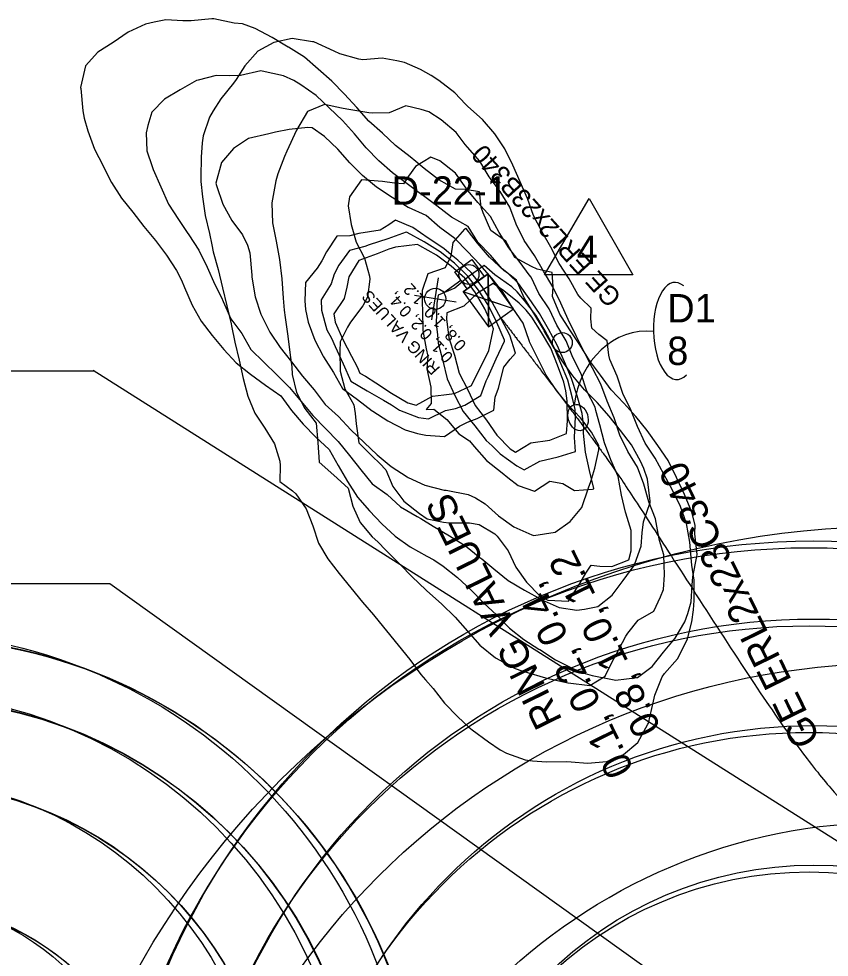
# Model space of a CAD drawing. Extents: x 1638506 to 1658005, y 834807 to 846788.
# Drawn here: x 1640682.9 to 1641025.5, y 842698.3 to 843094.9 of the extents above; entities that cross this region are included whole.
import ezdxf

# ---------------------------------------------------------------- set-up
doc = ezdxf.new("R2010")
doc.units = 0
for name, color, linetype in [('Default', 7, 'Continuous'), ('Old_Level_1', 7, 'Continuous'), ('Old_Level_2', 7, 'Continuous'), ('Old_Level_4', 7, 'Continuous'), ('Scratch_Level_0', 7, 'Continuous')]:
    doc.layers.add(name, color=color, linetype=linetype)

msp = doc.modelspace()

# ---------------------------------------------------------------- linework, layer by layer
at = {"layer": 'Default'}
for p, q in [((1640881.43, 842964.72), (1640881.28, 842987.13)), ((1640857.47, 842967.73), (1640860.34, 842985.39)), ((1640869.79, 842984.38), (1640862.53, 842979.16)), ((1640891.96, 842972.29), (1640870.76, 842979.57)), ((1640867.71, 842975.13), (1640850.08, 842978.02)), ((1640858.89, 842976.55), (1640858.89, 842976.55)), ((1640863.36, 842975.84), (1640863.36, 842975.84)), ((1640507.38, 842946.07), (1640714.43, 842946.07)), ((1640714.3, 842946.43), (1641119.83, 842689.85)), ((1640511.86, 842856.33), (1640721.43, 842856.33)), ((1640721.43, 842856.33), (1641083.08, 842597.13))]:
    msp.add_line(p, q, dxfattribs=at)
for points in [[(1640942.48, 842986.7), (1640905.09, 842986.7), (1640923.92, 843018.97)], [(1640879.64, 842985.95), (1640872.4, 842980.75), (1640867.18, 842988.02), (1640874.42, 842993.22)], [(1640891.96, 842972.29), (1640881.28, 842987.13), (1640870.76, 842979.57), (1640881.43, 842964.72)], [(1640881.36, 842975.93), (1640870.76, 842979.57), (1640881.28, 842987.13)], [(1640881.36, 842975.93), (1640881.43, 842964.72), (1640891.96, 842972.29)]]:
    msp.add_lwpolyline(points, close=True, dxfattribs=at)
msp.add_circle((1640858.91, 842976.58), 4.47, dxfattribs=at)
for centre, major_axis, ratio, start_param, end_param in [((1640960.68, 842963), (-0.49, 20.52), 0.466223, 5.884886, 7.853982), ((1640947.33, 842928.43), (-3.78, -34.34), 0.862742, 3.141593, 4.712389), ((1640960.68, 842963), (-0.49, 20.52), 0.466223, 1.570796, 3.572354)]:
    msp.add_ellipse(centre, major_axis=major_axis, ratio=ratio, start_param=start_param, end_param=end_param, dxfattribs=at)
msp.add_ellipse((1640919.27, 842926.4), major_axis=(1.72, -5.4), ratio=0.730797, dxfattribs=at)
msp.add_open_spline([(1640886.69, 842968.5), (1640897.24, 842954.72), (1640925.4, 842917.63), (1640940.05, 842897.05), (1641010.95, 842786.59), (1641043.17, 842750.84), (1641071.53, 842733.99), (1641088.02, 842730.82), (1641100.31, 842731.82)], degree=2, dxfattribs=at)
at = {"layer": 'Old_Level_1'}
for points in [[(1640709, 843065.93), (1640709.04, 843065.43), (1640709.96, 843055.95), (1640710.49, 843052.87), (1640712.07, 843047.55), (1640714.94, 843039.83), (1640718.52, 843032.75), (1640718.71, 843032.34), (1640722.08, 843025.67), (1640726.29, 843019.16), (1640731.16, 843013.25), (1640735.74, 843007.08), (1640740.72, 843001.26), (1640745.26, 842995.06), (1640749.48, 842988.56), (1640751.64, 842984.45), (1640752.9, 842981.35), (1640756.1, 842973.92), (1640759.92, 842967.07), (1640764.64, 842961.03), (1640769.6, 842955.19), (1640774.73, 842949.52), (1640780.88, 842944.77), (1640787.18, 842940.15), (1640793.59, 842935.63), (1640798.15, 842929.44), (1640803.06, 842923.56), (1640808.4, 842918.08), (1640814.09, 842912.91), (1640817.94, 842906.08), (1640821.89, 842899.34), (1640825.99, 842892.73), (1640831.11, 842887.05), (1640836.41, 842881.53), (1640841.94, 842876.21), (1640848.37, 842871.71), (1640855.43, 842867.78), (1640858.39, 842866.21), (1640862.26, 842863.64), (1640868.29, 842858.78), (1640874, 842853.63), (1640879.28, 842848.09), (1640884.95, 842842.9), (1640890.34, 842837.45), (1640896.38, 842832.61), (1640902.68, 842828.57), (1640903.07, 842828.34), (1640909.75, 842824.06), (1640917.13, 842820.42), (1640922.26, 842818.3), (1640925.27, 842817.46), (1640934.6, 842815.58), (1640935.1, 842815.49), (1640944.4, 842816.61), (1640950.57, 842821.19), (1640955.43, 842827.22), (1640960.39, 842833.14), (1640964.39, 842840.12), (1640965.62, 842843.58), (1640967.15, 842848.48), (1640967.47, 842855.56), (1640967.87, 842859.1), (1640969.53, 842867.73), (1640969.66, 842868.53), (1640968.66, 842877.25), (1640968.81, 842880.9), (1640967.38, 842886.4), (1640964.26, 842893.89), (1640960.89, 842901.08), (1640960.87, 842901.13), (1640957.4, 842908.31), (1640952.99, 842914.63), (1640948.55, 842920.93), (1640943.67, 842926.83), (1640938.57, 842932.54), (1640933.34, 842938.11), (1640928.83, 842944.35), (1640924.19, 842950.47), (1640920.1, 842957.09), (1640918.3, 842959.67), (1640915.74, 842963.46), (1640911.64, 842970.06), (1640908.49, 842977.52), (1640908.76, 842981.66), (1640908.33, 842987.68), (1640902, 842989.14), (1640899.66, 842990.16), (1640892.6, 842994.1), (1640888.73, 843000.91), (1640882.35, 843005.46), (1640879.15, 843012.87), (1640878.38, 843015.31), (1640877.57, 843021.75), (1640871.62, 843022.8), (1640867.48, 843022.95), (1640860.38, 843026.85), (1640854.23, 843031.6), (1640850.72, 843034.53), (1640848.33, 843036.58), (1640842.17, 843041.32), (1640836.56, 843046.56), (1640830.81, 843051.68), (1640825.79, 843057.46), (1640820.63, 843063.11), (1640815.26, 843068.56), (1640809.45, 843073.62), (1640803.61, 843078.65), (1640796.82, 843082.84), (1640796.77, 843082.87), (1640789.97, 843086.95), (1640782.83, 843090.82), (1640777.5, 843092.8), (1640773.86, 843093.02), (1640765.29, 843094.91), (1640764.48, 843094.86), (1640755.72, 843094.09), (1640752.16, 843094.05), (1640745.09, 843094.46), (1640740.06, 843093.42), (1640736.49, 843092.56), (1640729.14, 843089.29), (1640722.75, 843084.95), (1640716.24, 843080.74), (1640711.06, 843075.07), (1640709, 843065.93)], [(1640739.11, 843055.41), (1640737.48, 843049.87), (1640736.69, 843046.67), (1640737.02, 843039.16), (1640739.2, 843032.48), (1640739.72, 843031.28), (1640742.92, 843023.86), (1640746.22, 843016.54), (1640750.44, 843010.05), (1640754.12, 843004.54), (1640754.72, 843003.6), (1640758.97, 842997.13), (1640762.48, 842989.99), (1640765.77, 842982.66), (1640768.53, 842977.16), (1640769.25, 842975.49), (1640772.49, 842968.11), (1640777.11, 842961.98), (1640781.02, 842955.19), (1640786.42, 842949.77), (1640791.93, 842944.44), (1640797.38, 842939.05), (1640802.27, 842933.16), (1640807.11, 842927.22), (1640812.53, 842921.81), (1640817.89, 842916.34), (1640822.69, 842910.37), (1640827.43, 842904.34), (1640832.28, 842898.41), (1640838.63, 842893.84), (1640844.26, 842888.61), (1640851.27, 842884.64), (1640852.86, 842883.76), (1640858.05, 842880.45), (1640865.01, 842876.43), (1640871.75, 842872.21), (1640877.75, 842867.32), (1640878.63, 842866.63), (1640883.73, 842862.41), (1640889.76, 842857.55), (1640896.71, 842853.51), (1640903.77, 842849.58), (1640904.9, 842848.94), (1640911.32, 842846.1), (1640918.76, 842845), (1640922.03, 842845.45), (1640927.7, 842846.51), (1640933.7, 842851.28), (1640938.42, 842857.48), (1640942.95, 842863.88), (1640943.24, 842864.6), (1640945.93, 842871.99), (1640946.33, 842877.7), (1640946.95, 842882.28), (1640949.81, 842890.52), (1640949.77, 842891.11), (1640948.63, 842900.39), (1640947.15, 842904.88), (1640945.68, 842908.03), (1640941.83, 842914.86), (1640937.17, 842920.97), (1640932.46, 842927.02), (1640927.34, 842932.7), (1640921.99, 842938.18), (1640917.1, 842944.07), (1640912.62, 842950.33), (1640908.54, 842956.96), (1640904.94, 842963.06), (1640904.64, 842963.74), (1640900.66, 842970.46), (1640896.54, 842977.04), (1640893.33, 842984.44), (1640887.16, 842989.18), (1640882.25, 842995.06), (1640876.9, 843000.54), (1640872.82, 843007.16), (1640865.78, 843011.11), (1640859.65, 843015.88), (1640853.38, 843020.53), (1640852.73, 843020.89), (1640847.03, 843025.1), (1640840.85, 843029.83), (1640835.07, 843034.92), (1640829.72, 843040.39), (1640824.81, 843046.27), (1640819.68, 843051.94), (1640814.14, 843057.25), (1640808.54, 843062.5), (1640802.14, 843067.02), (1640799.16, 843068.81), (1640794.84, 843070.74), (1640785.72, 843072.81), (1640785.14, 843072.92), (1640776.65, 843070.91), (1640772.04, 843070.77), (1640766.31, 843070.95), (1640758.69, 843069.02), (1640757.94, 843068.81), (1640751.11, 843064.95), (1640744.47, 843060.89), (1640739.11, 843055.41)], [(1640766.18, 843025.43), (1640766.42, 843024.47), (1640769.07, 843016.55), (1640772.91, 843009.72), (1640777.49, 843003.54), (1640779.56, 842999.19), (1640780.61, 842996.05), (1640781.45, 842986.51), (1640781.39, 842985.75), (1640782.73, 842977.35), (1640785.23, 842970.08), (1640785.49, 842969.54), (1640789.03, 842962.43), (1640793.37, 842956.04), (1640798.09, 842949.99), (1640802.78, 842943.93), (1640807.79, 842938.14), (1640812.37, 842931.97), (1640818.04, 842926.78), (1640823.29, 842921.21), (1640828.84, 842915.92), (1640834.38, 842910.61), (1640840.3, 842905.65), (1640847.01, 842901.4), (1640847.52, 842901.09), (1640854.5, 842897.86), (1640862.71, 842895.67), (1640863.47, 842895.65), (1640872.89, 842893.85), (1640875.89, 842892.48), (1640880.01, 842889.97), (1640885.69, 842884.8), (1640892.1, 842880.27), (1640899.7, 842876.83), (1640900.63, 842876.5), (1640909.61, 842877.97), (1640915.91, 842882.41), (1640920.88, 842888.32), (1640923.68, 842896.64), (1640924.69, 842899.39), (1640926.36, 842905.08), (1640928.05, 842912.73), (1640928.1, 842914.57), (1640924.92, 842920.21), (1640920.26, 842926.31), (1640915.03, 842931.89), (1640910.22, 842937.86), (1640905.87, 842944.24), (1640902.27, 842951.29), (1640898.75, 842958.43), (1640898.7, 842958.55), (1640896.06, 842966.3), (1640891.67, 842972.64), (1640887.64, 842979.31), (1640882.82, 842985.27), (1640877.82, 842991.06), (1640872.57, 842996.62), (1640867.14, 843002.03), (1640860.91, 843006.71), (1640855.04, 843011.72), (1640847.61, 843015.14), (1640847.49, 843015.21), (1640840.75, 843019.43), (1640834.11, 843023.74), (1640828.2, 843028.71), (1640822.75, 843034.1), (1640817.73, 843039.87), (1640812.14, 843045.13), (1640806.86, 843048.87), (1640805.01, 843049), (1640797.23, 843048.11), (1640791.4, 843047.02), (1640788.56, 843046.3), (1640780.01, 843044.36), (1640773.62, 843040.02), (1640768.56, 843034.21), (1640766.18, 843025.43)], [(1640812.92, 842996.49), (1640811.04, 842992.61), (1640808.94, 842989.48), (1640804.01, 842983.53), (1640803.73, 842975.7), (1640804.05, 842972.06), (1640805.16, 842966.68), (1640808.09, 842959.03), (1640811.58, 842952.31), (1640811.74, 842952.02), (1640815.87, 842945.43), (1640819.72, 842938.61), (1640826.12, 842934.08), (1640832.25, 842929.3), (1640832.53, 842929.11), (1640838.85, 842924.96), (1640846.17, 842921.26), (1640851.41, 842919.61), (1640855, 842918.92), (1640862.81, 842918.4), (1640869.23, 842922.7), (1640872.56, 842924.47), (1640876.61, 842925.94), (1640883.63, 842929.58), (1640884.3, 842935.07), (1640885.63, 842938.79), (1640887.93, 842947.65), (1640890.62, 842951.09), (1640892.81, 842953.66), (1640890.48, 842961.26), (1640886.73, 842968.18), (1640883.03, 842975.15), (1640880.69, 842978.5), (1640878.72, 842981.57), (1640874.1, 842987.7), (1640868.47, 842992.93), (1640865.62, 842995.19), (1640862.52, 842997.86), (1640855.97, 843002.25), (1640849.47, 843006.69), (1640842.14, 843009.78), (1640839.36, 843007.87), (1640835.66, 843005.54), (1640826.62, 843004.15), (1640822.78, 843003.21), (1640817.25, 843003.11), (1640812.92, 842996.49)], [(1640818.1, 842990.75), (1640816.26, 842987.01), (1640814.94, 842982.84), (1640810.7, 842976.11), (1640810.84, 842971.82), (1640813.07, 842963.52), (1640815.05, 842959.88), (1640816.59, 842956.39), (1640819.94, 842949.11), (1640823.29, 842941.83), (1640830.19, 842937.75), (1640837.09, 842933.68), (1640840.4, 842931.8), (1640843.83, 842929.45), (1640851.85, 842926.39), (1640856.11, 842925.81), (1640863.24, 842929.34), (1640867.52, 842930.23), (1640871.43, 842931.68), (1640878.14, 842935.66), (1640880.42, 842941.87), (1640881.28, 842943.6), (1640884.7, 842951.23), (1640888.26, 842958.7), (1640888.13, 842959.14), (1640884.94, 842966.57), (1640881.48, 842973.75), (1640877.26, 842980.24), (1640872.57, 842986.32), (1640867, 842991.6), (1640860.97, 842996.46), (1640854.18, 843000.63), (1640847.12, 843004.56), (1640846.69, 843004.74), (1640838.9, 843001.96), (1640830.96, 842999.34), (1640829.16, 842998.66), (1640822.74, 842997.02), (1640818.1, 842990.75)], [(1640822.45, 842985.93), (1640821.55, 842981.48), (1640820.44, 842976.74), (1640815.99, 842970.25), (1640816.6, 842966.71), (1640819.91, 842959.39), (1640823.55, 842952.37), (1640825.97, 842947.79), (1640827.02, 842945.2), (1640829.49, 842943.88), (1640833.8, 842941.01), (1640840.41, 842936.67), (1640847.36, 842932.64), (1640850.82, 842931.67), (1640857.73, 842935.44), (1640862.56, 842936.06), (1640867.08, 842936.5), (1640874.26, 842939.96), (1640877.88, 842947.36), (1640880.32, 842952.09), (1640881.51, 842954.76), (1640883.61, 842963.86), (1640883.14, 842964.95), (1640879.92, 842972.34), (1640875.95, 842979.06), (1640871.39, 842985.26), (1640865.69, 842990.42), (1640859.42, 842995.06), (1640852.39, 842999.02), (1640851.35, 842999.59), (1640842.09, 842998.43), (1640839.31, 842997.52), (1640834.36, 842995.57), (1640826.63, 842992.72), (1640822.45, 842985.93)]]:
    msp.add_lwpolyline(points, dxfattribs=at)
for centre, radius in [((1640873.16, 842986.85), 4.21), ((1641016.92, 842574.38), 297), ((1641016.92, 842574.38), 264), ((1640635.3, 842614.58), 219), ((1640635.3, 842614.58), 193), ((1641016.92, 842574.38), 219), ((1640635.3, 842614.58), 157), ((1641016.92, 842574.38), 160), ((1640635.3, 842614.58), 106)]:
    msp.add_circle(centre, radius, dxfattribs=at)
at = {"layer": 'Old_Level_2'}
msp.add_arc((1640787.74, 844492.39), 1882, 251.76578, 273.94492, dxfattribs=at)
at = {"layer": 'Old_Level_4'}
for centre, radius in [((1641051.91, 842515.45), 365), ((1640629.86, 842616.81), 219), ((1641051.91, 842515.45), 307), ((1640629.86, 842616.81), 193), ((1640629.86, 842616.81), 157), ((1641051.91, 842515.45), 240), ((1640629.86, 842616.81), 106)]:
    msp.add_circle(centre, radius, dxfattribs=at)
at = {"layer": 'Scratch_Level_0'}
for points in [[(1640778.45, 843075.07), (1640774.74, 843069.31), (1640773.58, 843067.65), (1640768.3, 843061.04), (1640765.04, 843056.02), (1640763.54, 843053.37), (1640760.86, 843045.45), (1640760.36, 843042.5), (1640759.99, 843036.49), (1640759.85, 843027.91), (1640759.87, 843026.15), (1640760.5, 843019.7), (1640761.65, 843011.74), (1640763.56, 843004.15), (1640764.49, 842999.39), (1640765.07, 842996.38), (1640767.18, 842988.89), (1640769.03, 842981.27), (1640770.88, 842973.66), (1640772.6, 842965.98), (1640772.78, 842965.18), (1640774.25, 842958.27), (1640776.04, 842950.62), (1640777.79, 842942.96), (1640779.72, 842935.38), (1640782.65, 842928.3), (1640786.92, 842921.88), (1640790.92, 842915.31), (1640793.19, 842907.91), (1640793.3, 842906.08), (1640793.25, 842899.42), (1640798.56, 842895.38), (1640799.94, 842894.18), (1640804.41, 842887.85), (1640807.16, 842880.68), (1640809.64, 842873.37), (1640813.46, 842866.73), (1640818.28, 842860.57), (1640823.27, 842854.5), (1640828.23, 842848.41), (1640832.8, 842843.03), (1640833.32, 842842.39), (1640838.35, 842836.34), (1640843.25, 842830.22), (1640848.14, 842824.1), (1640852.79, 842817.86), (1640854.82, 842815.56), (1640858.02, 842811.91), (1640862.86, 842805.76), (1640868.45, 842799.99), (1640873.18, 842795.55), (1640874.56, 842794.46), (1640881.43, 842789.32), (1640886.42, 842785.95), (1640889.06, 842784.54), (1640896.97, 842781.82), (1640899.99, 842781.39), (1640905.94, 842780.9), (1640914.4, 842781.04), (1640916.43, 842780.94), (1640923.25, 842780.37), (1640931.45, 842781.03), (1640938.49, 842784.05), (1640944.52, 842789.13), (1640948.78, 842796.84), (1640949.03, 842797.29), (1640951.16, 842806.53), (1640951.78, 842809.05), (1640954.85, 842816.87), (1640955.76, 842818.3), (1640961.28, 842824.41), (1640964.1, 842829.94), (1640965.6, 842832.96), (1640967.39, 842840.08), (1640968.13, 842845.16), (1640968.34, 842849.07), (1640968.41, 842857.62), (1640967.37, 842864.06), (1640967.21, 842865.56), (1640966.59, 842873.78), (1640965.1, 842881.57), (1640962.59, 842888.86), (1640959.22, 842895.73), (1640955.49, 842902.42), (1640951.89, 842909.17), (1640947.62, 842915.6), (1640944.44, 842922.56), (1640941.56, 842929.67), (1640938.26, 842936.57), (1640935.75, 842943.86), (1640932.72, 842950.89), (1640932.28, 842952.82), (1640931.6, 842958.87), (1640928.03, 842961.47), (1640925.06, 842964.18), (1640924.73, 842968.18), (1640924.85, 842972.6), (1640920.48, 842976.83), (1640919.22, 842978.36), (1640915.51, 842985.06), (1640911.27, 842991.5), (1640907.83, 842998.33), (1640903.96, 843004.95), (1640900.39, 843011.72), (1640897.91, 843019.03), (1640894.76, 843026), (1640891.75, 843033.05), (1640888.37, 843039.91), (1640884.13, 843046.35), (1640878.88, 843052.29), (1640872.75, 843057.81), (1640871.66, 843058.85), (1640867.2, 843063.6), (1640860.39, 843068.78), (1640857.17, 843070.99), (1640852.69, 843073.52), (1640845.96, 843076.45), (1640842.65, 843077.11), (1640836.55, 843078.25), (1640828.34, 843077.62), (1640826.65, 843077.77), (1640818.59, 843080.11), (1640816.22, 843081.17), (1640807.6, 843085.13), (1640807.09, 843085.21), (1640798.39, 843086.54), (1640790.68, 843084.88), (1640783.99, 843081.15), (1640778.45, 843075.07)], [(1640800.34, 843047.86), (1640800.3, 843047.78), (1640796.2, 843038.95), (1640795.24, 843036.77), (1640792.39, 843029.36), (1640791.48, 843026.4), (1640789.91, 843017.1), (1640789.91, 843017.06), (1640790.12, 843008.68), (1640791.64, 843000.91), (1640793.13, 842993.15), (1640793.14, 842993.12), (1640794.1, 842985.07), (1640794.58, 842976.78), (1640795.12, 842971.76), (1640795.48, 842968.7), (1640796.6, 842960.72), (1640797.61, 842952.7), (1640798.35, 842947.83), (1640798.47, 842944.59), (1640800.23, 842936.94), (1640803.85, 842930.19), (1640808.62, 842924.01), (1640809.31, 842915.83), (1640809.83, 842907.56), (1640816.06, 842902.1), (1640822.11, 842896.55), (1640824.09, 842889), (1640827.22, 842882.01), (1640832.2, 842875.94), (1640834.69, 842873.87), (1640838.09, 842870.3), (1640843.83, 842864.6), (1640849.46, 842858.84), (1640851.66, 842856.69), (1640855.3, 842853.19), (1640861.57, 842847.75), (1640867.36, 842842.07), (1640867.38, 842842.04), (1640872.61, 842836.12), (1640877.83, 842830.17), (1640884.34, 842824.88), (1640884.37, 842824.85), (1640892.69, 842820.42), (1640895.58, 842819.33), (1640903.19, 842817.06), (1640905.51, 842816.48), (1640915, 842814.34), (1640915.1, 842814.32), (1640924.2, 842813.14), (1640930.8, 842817.05), (1640934.04, 842823.69), (1640935.09, 842825.66), (1640939.5, 842834.04), (1640940.29, 842835.29), (1640944.7, 842840.8), (1640951.36, 842844.59), (1640954.11, 842850.6), (1640955.36, 842853.8), (1640955.83, 842859.97), (1640955.52, 842868.34), (1640953.77, 842874.38), (1640953.45, 842875.85), (1640951.95, 842883.63), (1640949.17, 842890.79), (1640947.11, 842898.3), (1640944.4, 842905.49), (1640940.35, 842912.03), (1640936.97, 842918.89), (1640934.58, 842926.24), (1640931.64, 842933.32), (1640928.92, 842940.51), (1640925.45, 842947.32), (1640921.89, 842954.1), (1640918.46, 842960.93), (1640915.14, 842967.83), (1640911.95, 842974.78), (1640908.68, 842981.7), (1640904.65, 842988.24), (1640900.85, 842994.9), (1640896.49, 843001.28), (1640893.12, 843008.15), (1640890.42, 843015.35), (1640886.39, 843021.89), (1640881.7, 843028.11), (1640877.73, 843034.68), (1640872.49, 843040.63), (1640871.52, 843041.78), (1640867.81, 843046.85), (1640861.37, 843052.21), (1640856.2, 843055.61), (1640852.9, 843056.57), (1640846.47, 843058.07), (1640839.4, 843055.12), (1640832.34, 843055), (1640830.87, 843055.13), (1640821.54, 843056.76), (1640819.34, 843057.13), (1640812.1, 843058.62), (1640804.97, 843055.79), (1640800.34, 843047.86)], [(1640822.7, 843019.71), (1640822.18, 843015.91), (1640823.33, 843007.95), (1640825.49, 843000.49), (1640829.05, 842993.72), (1640831.08, 842986.19), (1640831.27, 842984.92), (1640830.29, 842977.28), (1640828.32, 842973.58), (1640823.16, 842966.74), (1640821.88, 842964.62), (1640818.76, 842958.34), (1640818.58, 842954.48), (1640818.67, 842946), (1640820.76, 842938.5), (1640824.5, 842931.82), (1640825.05, 842928.18), (1640825.53, 842923.8), (1640826.57, 842915.78), (1640832.27, 842910.06), (1640835.46, 842907.01), (1640837.99, 842904.35), (1640841, 842897.31), (1640845.66, 842891.07), (1640852.32, 842885.82), (1640855.49, 842883.59), (1640862.37, 842882.23), (1640864.82, 842881.94), (1640873.39, 842881.85), (1640877.52, 842881.16), (1640884.17, 842877.26), (1640885.05, 842876.33), (1640889.78, 842870.13), (1640892.96, 842863.17), (1640897.55, 842856.9), (1640903.14, 842851.13), (1640906.47, 842849.22), (1640915.19, 842848.81), (1640920.06, 842856.25), (1640922.63, 842860.7), (1640924.8, 842863.96), (1640928.56, 842863.61), (1640933.58, 842863.43), (1640940.73, 842866.23), (1640941.8, 842870.12), (1640941.75, 842878.62), (1640939.46, 842886.02), (1640939.36, 842886.37), (1640937.62, 842893.64), (1640936.19, 842901.46), (1640933.17, 842908.5), (1640930.5, 842915.71), (1640928.54, 842923.27), (1640926.74, 842929.39), (1640926.46, 842930.77), (1640922.95, 842937.57), (1640920.53, 842944.9), (1640917.11, 842951.75), (1640914.23, 842958.85), (1640910.36, 842965.48), (1640907.03, 842972.37), (1640902.71, 842978.77), (1640899.47, 842985.7), (1640898.55, 842986.76), (1640894.81, 842991.93), (1640890.02, 842998.1), (1640885.94, 843004.62), (1640882.21, 843011.31), (1640876.9, 843017.23), (1640872.2, 843023.04), (1640871.99, 843023.34), (1640867.53, 843029.67), (1640860.84, 843034.9), (1640857.1, 843036.43), (1640850.52, 843032.48), (1640847.59, 843028.4), (1640845.57, 843025.21), (1640841.67, 843025.49), (1640836.57, 843026.17), (1640827.71, 843026.86), (1640822.7, 843019.71)], [(1640871.89, 843006.34), (1640871.34, 843005.97), (1640866.29, 843000.39), (1640865.57, 842994.61), (1640863.06, 842989.6), (1640855.74, 842987.16), (1640853.42, 842980.12), (1640853.36, 842974.67), (1640853.52, 842971.65), (1640853.62, 842963.17), (1640855.1, 842955.37), (1640855.79, 842952.36), (1640855.32, 842946.96), (1640857.02, 842939.27), (1640857.13, 842932.28), (1640855.09, 842929.8), (1640858.31, 842929.9), (1640863.77, 842925.54), (1640868.82, 842919.5), (1640873.38, 842916.56), (1640875.34, 842914.18), (1640880.61, 842908.24), (1640887.26, 842902.99), (1640889.55, 842901.01), (1640893.9, 842897.73), (1640900.9, 842895.26), (1640907.3, 842899.57), (1640912.8, 842898.49), (1640917.81, 842895.53), (1640925.32, 842896.12), (1640925.94, 842896.33), (1640925.94, 842896.42), (1640924.06, 842904.02), (1640922.39, 842911.72), (1640921.61, 842919.86), (1640921.69, 842922.32), (1640921.09, 842928.13), (1640918.87, 842935.57), (1640916.52, 842942.93), (1640913.5, 842949.97), (1640910.45, 842957), (1640906.75, 842963.7), (1640903.03, 842970.4), (1640898.63, 842976.76), (1640894.1, 842983.06), (1640889.87, 842987.09), (1640887.87, 842988.52), (1640881.9, 842994.11), (1640876.83, 843000.14), (1640871.96, 843006.28), (1640871.89, 843006.34)], [(1640860.17, 842978.15), (1640859.66, 842974.66), (1640859.34, 842965.98), (1640859.92, 842961.3), (1640860.16, 842957.86), (1640862.13, 842950.3), (1640863.98, 842942.69), (1640867.17, 842935.74), (1640870.72, 842928.96), (1640875.62, 842922.84), (1640880.4, 842916.66), (1640882.98, 842914.38), (1640886.33, 842911.05), (1640893.4, 842906), (1640896.47, 842904.27), (1640903.15, 842908.02), (1640910.83, 842909.73), (1640918.23, 842912.02), (1640917.82, 842918), (1640918.24, 842926.73), (1640918, 842929.84), (1640916.89, 842934.59), (1640914.9, 842942.14), (1640912.07, 842949.27), (1640909.11, 842956.34), (1640905.32, 842963), (1640901.4, 842969.6), (1640896.65, 842975.79), (1640893.57, 842979.57), (1640891.26, 842981.66), (1640884.08, 842986.66), (1640879.6, 842990.64), (1640873.26, 842986.19), (1640867.22, 842981.14), (1640860.17, 842978.15)], [(1640863.85, 842970.65), (1640863.62, 842968.08), (1640864.68, 842960.08), (1640867.06, 842952.72), (1640869.07, 842945.19), (1640872.62, 842938.41), (1640875.81, 842931.46), (1640880.55, 842925.26), (1640884.92, 842918.89), (1640890.61, 842913.16), (1640892.78, 842911.77), (1640899.36, 842915.74), (1640907.3, 842916.91), (1640914.47, 842919.67), (1640914.86, 842925.07), (1640914.69, 842933.51), (1640914.14, 842937.69), (1640913.27, 842941.34), (1640910.65, 842948.57), (1640907.76, 842955.68), (1640903.9, 842962.3), (1640899.78, 842968.8), (1640897.42, 842971.72), (1640894.45, 842974.71), (1640887.88, 842980), (1640883.36, 842982.99), (1640876.79, 842979.01), (1640871.01, 842973.43), (1640863.85, 842970.65)]]:
    msp.add_lwpolyline(points, dxfattribs=at)
for centre, radius in [((1640912.65, 842958.08), 4.21), ((1641018.82, 842577.25), 297), ((1641018.82, 842577.25), 264), ((1640634.95, 842614.89), 219), ((1640634.95, 842614.89), 193), ((1641018.82, 842577.25), 219), ((1640634.95, 842614.89), 157), ((1641018.82, 842577.25), 160), ((1640634.95, 842614.89), 106)]:
    msp.add_circle(centre, radius, dxfattribs=at)

# ---------------------------------------------------------------- texts
at = {"layer": 'Default'}
for s, p in [('D-22-1', (1640840.51, 843016.31)), ('4', (1640918.74, 842991.31)), ('D1', (1640956.97, 842966.6)), ('8', (1640956.97, 842948.6))]:
    msp.add_text(s, height=12, dxfattribs=at).set_placement(p)
at = {"layer": 'Old_Level_1'}
for s, height, p in [('GE ERL2x23B340', 8, (1640938.13, 842977.59)), ('0.8, 1.0, 1.2', 5, (1640872.4, 842957.31)), ('RING VALUES', 5, (1640861.27, 842947.25)), ('0.1, 0.2, 0.4,', 5, (1640866.84, 842952.28))]:
    msp.add_text(s, height=height, rotation=132.0759, dxfattribs=at).set_placement(p)
at = {"layer": 'Scratch_Level_0'}
for s, p in [('GE ERL2x23C340', (1641021.98, 842790.51)), ('RING VALUES', (1640912.81, 842798.57)), ('0.8, 1.0, 1.2', (1640954.56, 842795.24)), ('0.1, 0.2, 0.4,', (1640943.06, 842777.81))]:
    msp.add_text(s, height=12, rotation=116.1669, dxfattribs=at).set_placement(p)

doc.saveas('drawing.dxf')
